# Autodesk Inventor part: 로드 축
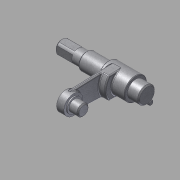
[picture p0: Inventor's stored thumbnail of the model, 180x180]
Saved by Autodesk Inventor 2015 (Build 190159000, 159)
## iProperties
Created: 2015-10
Part Number: 로드 축
Document SubType Name: Modeling
Designer: mdu
Density: 7.86 g/cm^3
Material: 강철, 연강
Mass: 157.934 g
Surface Area: 69.4485 cm^2
Volume: 20.0934 cm^3
Appearance: 금속-강(스테인리스, 브러시됨)
Author: mdu
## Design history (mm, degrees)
sketch "스케치1"
  geometry: L1 (-3.325, 13.5)-(-3.325, -13.5) reference; L2 (48.675, -15.7)-(48.675, 15.7) reference; L3 (48.675, 0)-(-26.325, 0); L4 (39.675, -18.06)-(39.675, 18.06) reference; L5 (15.675, 18.855)-(15.675, -18.855) reference; L6 (6.675, 15.7)-(6.675, -15.7) reference; L7 (3.675, -10)-(3.675, 10) reference; L8 (49.675, 7.5)-(39.675, 7.5); L9 (39.675, 7.5)-(39.675, 10); L10 (39.675, 10)-(15.675, 10); L11 (15.675, 10)-(15.675, 7.5); L12 (15.675, 7.5)-(-4.325, 7.5); L13 (-4.325, 7.5)-(-4.325, 6); L14 (-4.325, 6)-(-26.325, 6); L15 (-26.325, 6)-(-26.325, 0); L16 (48.675, 0)-(49.675, 0); L17 (49.675, 0)-(49.675, 7.5); 1 further point
  constraints: 22 end point, 7 perpendicular, 4 point on line, 2 parallel, 1 collinear, 1 midpoint
  dimensions: "d0" = 15 diameter of L8 L3; "d1" = 20 diameter of L10 L3; "d2" = 12 diameter of L14 L3; "d3" = 20 distance of L11.end L12.end; "d4" = 1 distance between parallel lines of L17 L2; "d5" = 75 distance of L3.start L3.end
revolve "회전1" sketch "스케치1" stored, may be unused: angle "d6" = 90 deg
chamfer "모따기1" distance "d7" = 1; stored, may be unused: second distance "d8" = 2, angle "d9" = 45 deg
node "작업 평면1"
sketch "스케치2"
  geometry: 1 further point
sketch "스케치3"
  geometry: L1 (9.993, -0.375)-(8.494, -40.319); L2 (-8.494, -40.319)-(-9.993, -0.375); C1 r 10 at (0, 0) reference; A1 r 8.5 centre (0, -40) between (8.494, -40.319) and (-8.494, -40.319); A2 r 10 centre (0, 0) between (-9.993, -0.375) and (9.993, -0.375) reference; 1 further point
  constraints: 4 end point, 4 point on circle, 4 tangent, 1 centre point, 1 vertical alignment
  dimensions: "d12" = 17 diameter of A1; "d22" = 40 distance of A1.centre A2.centre
  node "투영된 루프1"
extrude "돌출1" join sketch "스케치3" distance "d13" = 6.5; taper "d14" = 0 deg
node "작업 평면3"
  node "작업 평면2"
extrude "돌출2" join sketch "스케치3" stored distance "d17" = 6; taper "d18" = 0 deg
sketch "스케치7"
  geometry: L1 (-9.993, -0.375)-(-8.494, -40.319) reference; L2 (8.494, -40.319)-(9.993, -0.375) reference; A1 r 10 centre (0, 0) between (-9.993, -0.375) and (9.993, -0.375) reference; A2 r 15 centre (0, 0) between (-9.574, -11.547) and (9.574, -11.547); 1 further point
  constraints: 2 point on circle, 2 point on line, 1 centre point, 1 coincident
  dimensions: "d32" = 30 diameter of A2
extrude "돌출6" join sketch "스케치7" distance "d33" = 6; taper "d34" = 0 deg
sketch "스케치5"
  geometry: C1 r 5 at (0, 0) reference; C2 r 6.5 at (0, 0); 1 further point
  constraints: 1 centre point, 1 coincident
  dimensions: "d23" = 13 diameter of C2
  node "참조8"
extrude "돌출4" join sketch "스케치5" distance "d24" = 9; taper "d25" = 0 deg
extrude "돌출5" join sketch "스케치5" distance "d26" = 1; taper "d27" = 0 deg
fillet "모깎기1" dims "d28" = 1
chamfer "모따기2" distance "d29" = 1; stored, may be unused: second distance "d30" = 2, angle "d31" = 45 deg
chamfer "모따기3" distance "d35" = 0.5; stored, may be unused: second distance "d36" = 2, angle "d37" = 45 deg
sketch "스케치8"
  geometry: L1 (-3.25, 5.044)-(3.25, 5.044); L2 (5.044, 3.25)-(5.044, -3.25); L3 (3.25, -5.044)-(-3.25, -5.044); L4 (-5.044, -3.25)-(-5.044, 3.25); 2 further points
  constraints: 8 end point, 6 perpendicular, 1 horizontal, 9 other
  dimensions: "d38" = 6.5 distance of L3.start L3.end
extrude "돌출7" cut sketch "스케치8" distance "d39" = 15; taper "d40" = 0 deg
node "작업 평면4"
sketch "스케치9"
  geometry: L1 (7.66, 6.428)-(25.279, 21.212); L2 (23.973, 23.344)-(1.901, 9.818); L3 (27.152, 19.555)-(9.999, 0.167); L4 (28.659, 0)-(-16.444, 0) reference; C1 r 2 at (25.279, 21.212); A1 r 10 centre (0, 0) between (7.66, 6.428) and (1.901, 9.818) reference; A2 r 2.5 centre (25.279, 21.212) between (23.973, 23.344) and (27.152, 19.555); 1 further point
  constraints: 6 end point, 5 point on circle, 2 centre point, 2 coincident, 2 tangent, 1 point on line
  dimensions: "d42" = 23 distance of L1.start L1.end; "d43" = 5 diameter of A2; "d44" = 17 deg angle of L3 L2; "d45" = 8.5 deg angle of L1 L2 (= 0.5 x d44); "d46" = 40 deg angle of L4 L1; "d54" = 4 diameter of C1
extrude "돌출8" join sketch "스케치9" stored distance "d47" = 3; taper "d48" = 0 deg
extrude "돌출9" join sketch "스케치9" stored distance "d49" = 4; taper "d50" = 0 deg
fillet "모깎기2" dims "d51" = 1
fillet "모깎기3" dims "d52" = 1
fillet "모깎기4" dims "d53" = 1
extrude "돌출10" join sketch "스케치9" stored distance "d55" = 15; taper "d56" = 0 deg
chamfer "모따기4" distance "d57" = 0.5; stored, may be unused: second distance "d58" = 2, angle "d59" = 45 deg
node "솔리드1"
node "참조1"
node "참조2"
node "참조3"
node "참조4"
node "참조5"
node "참조6"
other parameters: "d10" = -8.5, "d15" = -1, "d16" = -3, "d41" = -15
